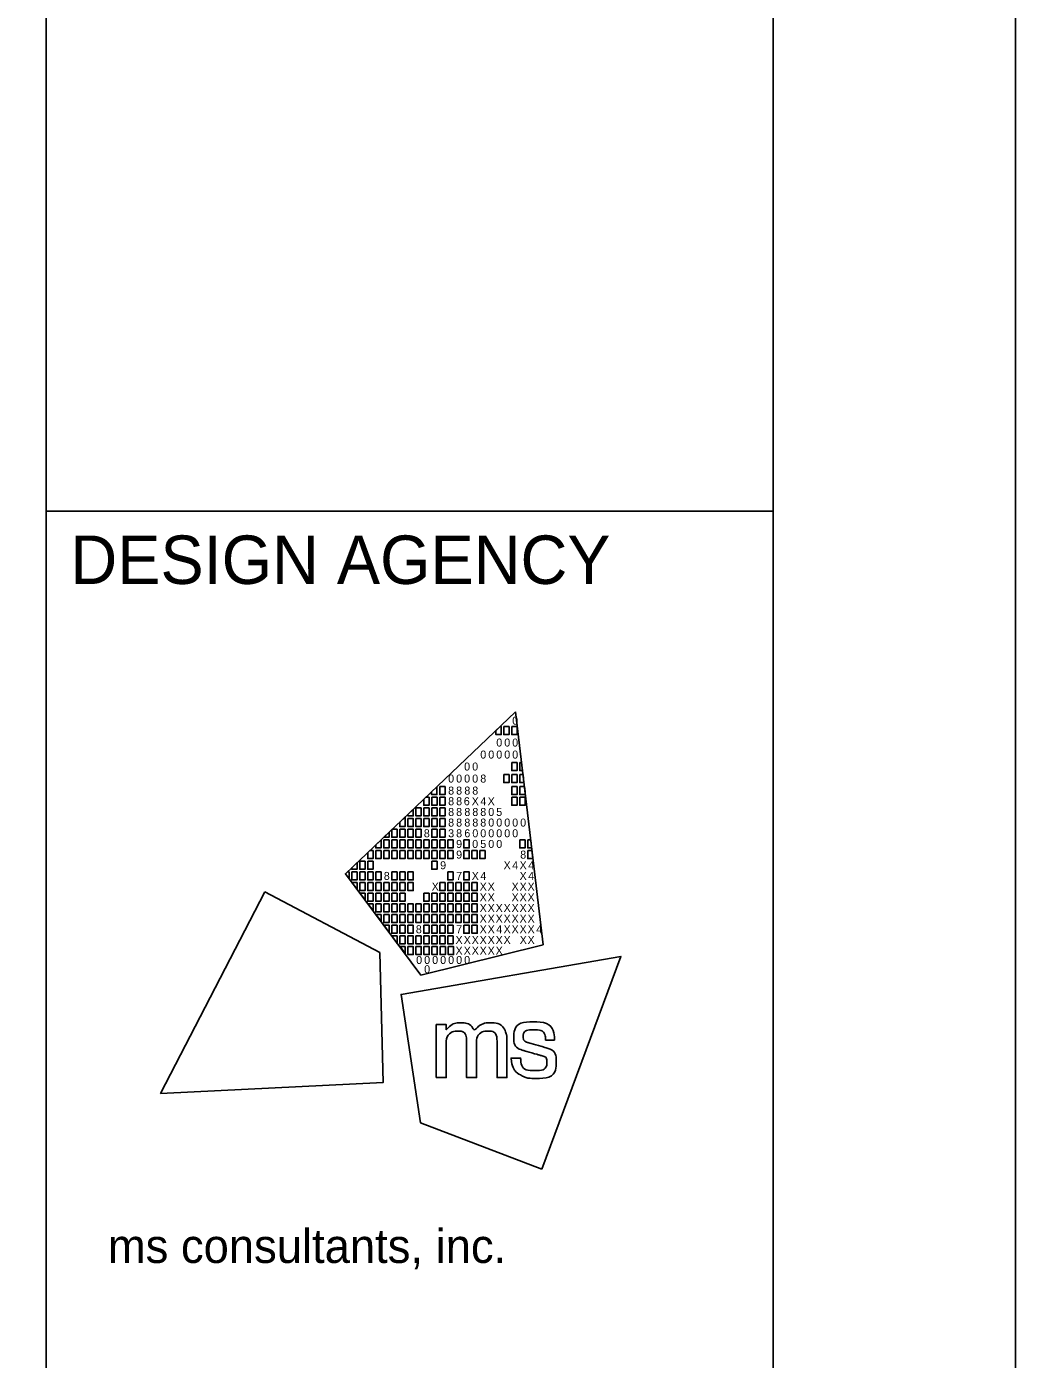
# Model space of a CAD drawing. Extents: x -10 to 89.7, y -4.8 to 22.
# Drawn here: x 31.96 to 34, y 2.75 to 5.5 of the extents above; entities that cross this region are included whole.
import ezdxf

# ---------------------------------------------------------------- set-up
doc = ezdxf.new("R2010")
doc.units = 0
for name, color, linetype in [('Default', 7, 'Continuous'), ('GM_X_Minor_Lake', 7, 'Continuous'), ('GM_X_Minor_River', 7, 'Continuous'), ('SH_Text', 7, 'Continuous')]:
    doc.layers.add(name, color=color, linetype=linetype)

msp = doc.modelspace()

# ---------------------------------------------------------------- linework, layer by layer
at = {"layer": 'Default'}
for p, q in [((32.6176, 3.7519), (32.9688, 4.0861)), ((32.9688, 4.0861), (32.9688, 4.0861)), ((32.9688, 4.0861), (33.0253, 3.6052)), ((32.773, 3.543), (32.6176, 3.7519)), ((33.0253, 3.6052), (32.773, 3.543))]:
    msp.add_line(p, q, dxfattribs=at)
for points in [[(32.9279, 4.0472), (32.9369, 4.0558), (32.939, 4.0558), (32.939, 4.0393), (32.9279, 4.0393)], [(32.9444, 4.0558), (32.9554, 4.0558), (32.9554, 4.0393), (32.9444, 4.0393)], [(32.9609, 4.0558), (32.9719, 4.0558), (32.9719, 4.0393), (32.9609, 4.0393)], [(32.9606, 3.9815), (32.9716, 3.9815), (32.9716, 3.965), (32.9606, 3.965)], [(32.9771, 3.9815), (32.9811, 3.9815), (32.983, 3.965), (32.9771, 3.965)], [(32.9442, 3.9567), (32.9552, 3.9567), (32.9552, 3.9402), (32.9442, 3.9402)], [(32.9606, 3.9567), (32.9716, 3.9567), (32.9716, 3.9402), (32.9606, 3.9402)], [(32.9771, 3.9567), (32.984, 3.9567), (32.9859, 3.9402), (32.9771, 3.9402)], [(32.7954, 3.9211), (32.8064, 3.9316), (32.8064, 3.9154), (32.7954, 3.9154)], [(32.7958, 3.9099), (32.8068, 3.9099), (32.8068, 3.8934), (32.7958, 3.8934)], [(32.8123, 3.9319), (32.8233, 3.9319), (32.8233, 3.9154), (32.8123, 3.9154)], [(32.8123, 3.9099), (32.8233, 3.9099), (32.8233, 3.8934), (32.8123, 3.8934)], [(32.9606, 3.9319), (32.9716, 3.9319), (32.9716, 3.9154), (32.9606, 3.9154)], [(32.9606, 3.9099), (32.9716, 3.9099), (32.9716, 3.8934), (32.9606, 3.8934)], [(32.9771, 3.9319), (32.9869, 3.9319), (32.9881, 3.9218), (32.9881, 3.9154), (32.9771, 3.9154)], [(32.9771, 3.9099), (32.9881, 3.9099), (32.9881, 3.8934), (32.9771, 3.8934)], [(32.7628, 3.8879), (32.7738, 3.8879), (32.7738, 3.8714), (32.7628, 3.8714)], [(32.7793, 3.8879), (32.7903, 3.8879), (32.7903, 3.8714), (32.7793, 3.8714)], [(32.7958, 3.8879), (32.8068, 3.8879), (32.8068, 3.8714), (32.7958, 3.8714)], [(32.8123, 3.8879), (32.8233, 3.8879), (32.8233, 3.8714), (32.8123, 3.8714)], [(32.7463, 3.8659), (32.7573, 3.8659), (32.7573, 3.8494), (32.7463, 3.8494)], [(32.7628, 3.8659), (32.7738, 3.8659), (32.7738, 3.8494), (32.7628, 3.8494)], [(32.7793, 3.8659), (32.7903, 3.8659), (32.7903, 3.8494), (32.7793, 3.8494)], [(32.7958, 3.8659), (32.8068, 3.8659), (32.8068, 3.8494), (32.7958, 3.8494)], [(32.8123, 3.8659), (32.8233, 3.8659), (32.8233, 3.8494), (32.8123, 3.8494)], [(32.7297, 3.8439), (32.7407, 3.8439), (32.7407, 3.8273), (32.7297, 3.8273)], [(32.7463, 3.8439), (32.7573, 3.8439), (32.7573, 3.8273), (32.7463, 3.8273)], [(32.7628, 3.8439), (32.7738, 3.8439), (32.7738, 3.8273), (32.7628, 3.8273)], [(32.7958, 3.8439), (32.8068, 3.8439), (32.8068, 3.8273), (32.7958, 3.8273)], [(32.8123, 3.8439), (32.8233, 3.8439), (32.8233, 3.8273), (32.8123, 3.8273)], [(32.6802, 3.7998), (32.6912, 3.7998), (32.6912, 3.7833), (32.6802, 3.7833)], [(32.6967, 3.8218), (32.7077, 3.8218), (32.7077, 3.8053), (32.6967, 3.8053)], [(32.6967, 3.7998), (32.7077, 3.7998), (32.7077, 3.7833), (32.6967, 3.7833)], [(32.7132, 3.8218), (32.7242, 3.8218), (32.7242, 3.8053), (32.7132, 3.8053)], [(32.7132, 3.7998), (32.7242, 3.7998), (32.7242, 3.7833), (32.7132, 3.7833)], [(32.7297, 3.8218), (32.7407, 3.8218), (32.7407, 3.8053), (32.7297, 3.8053)], [(32.7297, 3.7998), (32.7407, 3.7998), (32.7407, 3.7833), (32.7297, 3.7833)], [(32.7463, 3.8218), (32.7573, 3.8218), (32.7573, 3.8053), (32.7463, 3.8053)], [(32.7463, 3.7998), (32.7573, 3.7998), (32.7573, 3.7833), (32.7463, 3.7833)], [(32.7628, 3.8218), (32.7738, 3.8218), (32.7738, 3.8053), (32.7628, 3.8053)], [(32.7628, 3.7998), (32.7738, 3.7998), (32.7738, 3.7833), (32.7628, 3.7833)], [(32.7793, 3.8218), (32.7903, 3.8218), (32.7903, 3.8053), (32.7793, 3.8053)], [(32.7793, 3.7998), (32.7903, 3.7998), (32.7903, 3.7833), (32.7793, 3.7833)], [(32.7958, 3.8218), (32.8068, 3.8218), (32.8068, 3.8053), (32.7958, 3.8053)], [(32.7958, 3.7998), (32.8068, 3.7998), (32.8068, 3.7833), (32.7958, 3.7833)], [(32.8123, 3.8218), (32.8233, 3.8218), (32.8233, 3.8053), (32.8123, 3.8053)], [(32.8123, 3.7998), (32.8233, 3.7998), (32.8233, 3.7833), (32.8123, 3.7833)], [(32.8288, 3.8218), (32.8398, 3.8218), (32.8398, 3.8053), (32.8288, 3.8053)], [(32.8288, 3.7998), (32.8398, 3.7998), (32.8398, 3.7833), (32.8288, 3.7833)], [(32.8618, 3.8218), (32.8729, 3.8218), (32.8729, 3.8053), (32.8618, 3.8053)], [(32.8618, 3.7998), (32.8729, 3.7998), (32.8729, 3.7833), (32.8618, 3.7833)], [(32.8784, 3.7998), (32.8894, 3.7998), (32.8894, 3.7833), (32.8784, 3.7833)], [(32.8947, 3.7998), (32.9057, 3.7998), (32.9057, 3.7833), (32.8947, 3.7833)], [(32.9771, 3.8218), (32.9881, 3.8218), (32.9881, 3.8053), (32.9771, 3.8053)], [(32.9936, 3.8218), (32.9999, 3.8218), (33.0018, 3.8053), (32.9936, 3.8053)], [(32.9936, 3.7998), (33.0024, 3.7998), (33.0044, 3.7833), (32.9936, 3.7833)], [(32.6472, 3.7778), (32.6582, 3.7778), (32.6582, 3.7613), (32.6472, 3.7613)], [(32.6637, 3.7778), (32.6747, 3.7778), (32.6747, 3.7613), (32.6637, 3.7613)], [(32.7958, 3.7778), (32.8068, 3.7778), (32.8068, 3.7613), (32.7958, 3.7613)], [(32.6307, 3.7558), (32.6417, 3.7558), (32.6417, 3.7393), (32.6307, 3.7393)], [(32.6472, 3.7558), (32.6582, 3.7558), (32.6582, 3.7393), (32.6472, 3.7393)], [(32.6637, 3.7558), (32.6747, 3.7558), (32.6747, 3.7393), (32.6637, 3.7393)], [(32.6802, 3.7558), (32.6912, 3.7558), (32.6912, 3.7393), (32.6802, 3.7393)], [(32.7132, 3.7558), (32.7242, 3.7558), (32.7242, 3.7393), (32.7132, 3.7393)], [(32.7297, 3.7558), (32.7407, 3.7558), (32.7407, 3.7393), (32.7297, 3.7393)], [(32.7463, 3.7558), (32.7573, 3.7558), (32.7573, 3.7393), (32.7463, 3.7393)], [(32.8288, 3.7558), (32.8398, 3.7558), (32.8398, 3.7393), (32.8288, 3.7393)], [(32.8618, 3.7558), (32.8729, 3.7558), (32.8729, 3.7393), (32.8618, 3.7393)], [(32.6307, 3.7338), (32.6417, 3.7338), (32.6417, 3.72)], [(32.6472, 3.7338), (32.6582, 3.7338), (32.6582, 3.7173), (32.6472, 3.7173)], [(32.6637, 3.7338), (32.6747, 3.7338), (32.6747, 3.7173), (32.6637, 3.7173)], [(32.6802, 3.7338), (32.6912, 3.7338), (32.6912, 3.7173), (32.6802, 3.7173)], [(32.6967, 3.7338), (32.7077, 3.7338), (32.7077, 3.7173), (32.6967, 3.7173)], [(32.7132, 3.7338), (32.7242, 3.7338), (32.7242, 3.7173), (32.7132, 3.7173)], [(32.7297, 3.7338), (32.7407, 3.7338), (32.7407, 3.7173), (32.7297, 3.7173)], [(32.7463, 3.7338), (32.7573, 3.7338), (32.7573, 3.7173), (32.7463, 3.7173)], [(32.8123, 3.7338), (32.8233, 3.7338), (32.8233, 3.7173), (32.8123, 3.7173)], [(32.8288, 3.7338), (32.8398, 3.7338), (32.8398, 3.7173), (32.8288, 3.7173)], [(32.8453, 3.7338), (32.8563, 3.7338), (32.8563, 3.7173), (32.8453, 3.7173)], [(32.8618, 3.7338), (32.8729, 3.7338), (32.8729, 3.7173), (32.8618, 3.7173)], [(32.8784, 3.7338), (32.8894, 3.7338), (32.8894, 3.7173), (32.8784, 3.7173)], [(32.6472, 3.7117), (32.6582, 3.7117), (32.6582, 3.698)], [(32.6637, 3.7117), (32.6747, 3.7117), (32.6747, 3.6952), (32.6637, 3.6952)], [(32.6637, 3.6897), (32.6747, 3.6897), (32.6747, 3.676)], [(32.6747, 3.6897), (32.6747, 3.6897), (32.6747, 3.6897)], [(32.6802, 3.7117), (32.6912, 3.7117), (32.6912, 3.6952), (32.6802, 3.6952)], [(32.6802, 3.6897), (32.6912, 3.6897), (32.6912, 3.6732), (32.6802, 3.6732)], [(32.6967, 3.7117), (32.7077, 3.7117), (32.7077, 3.6952), (32.6967, 3.6952)], [(32.6967, 3.6897), (32.7077, 3.6897), (32.7077, 3.6732), (32.6967, 3.6732)], [(32.7132, 3.7117), (32.7242, 3.7117), (32.7242, 3.6952), (32.7132, 3.6952)], [(32.7132, 3.6897), (32.7242, 3.6897), (32.7242, 3.6732), (32.7132, 3.6732)], [(32.7297, 3.7117), (32.7407, 3.7117), (32.7407, 3.6952), (32.7297, 3.6952)], [(32.7297, 3.6897), (32.7407, 3.6897), (32.7407, 3.6732), (32.7297, 3.6732)], [(32.7463, 3.6897), (32.7573, 3.6897), (32.7573, 3.6732), (32.7463, 3.6732)], [(32.7628, 3.6897), (32.7738, 3.6897), (32.7738, 3.6732), (32.7628, 3.6732)], [(32.7793, 3.7117), (32.7903, 3.7117), (32.7903, 3.6952), (32.7793, 3.6952)], [(32.7793, 3.6897), (32.7903, 3.6897), (32.7903, 3.6732), (32.7793, 3.6732)], [(32.7958, 3.7117), (32.8068, 3.7117), (32.8068, 3.6952), (32.7958, 3.6952)], [(32.7958, 3.6897), (32.8068, 3.6897), (32.8068, 3.6732), (32.7958, 3.6732)], [(32.8123, 3.7117), (32.8233, 3.7117), (32.8233, 3.6952), (32.8123, 3.6952)], [(32.8123, 3.6897), (32.8233, 3.6897), (32.8233, 3.6732), (32.8123, 3.6732)], [(32.8288, 3.7117), (32.8398, 3.7117), (32.8398, 3.6952), (32.8288, 3.6952)], [(32.8288, 3.6897), (32.8398, 3.6897), (32.8398, 3.6732), (32.8288, 3.6732)], [(32.8453, 3.7117), (32.8563, 3.7117), (32.8563, 3.6952), (32.8453, 3.6952)], [(32.8453, 3.6897), (32.8563, 3.6897), (32.8563, 3.6732), (32.8453, 3.6732)], [(32.8618, 3.7117), (32.8729, 3.7117), (32.8729, 3.6952), (32.8618, 3.6952)], [(32.8618, 3.6897), (32.8729, 3.6897), (32.8729, 3.6732), (32.8618, 3.6732)], [(32.8784, 3.7117), (32.8894, 3.7117), (32.8894, 3.6952), (32.8784, 3.6952)], [(32.8784, 3.6897), (32.8894, 3.6897), (32.8894, 3.6732), (32.8784, 3.6732)], [(32.6802, 3.6677), (32.6912, 3.6677), (32.6912, 3.654)], [(32.6967, 3.6677), (32.7077, 3.6677), (32.7077, 3.6512), (32.6967, 3.6512)], [(32.7132, 3.6677), (32.7242, 3.6677), (32.7242, 3.6512), (32.7132, 3.6512)], [(32.7297, 3.6677), (32.7407, 3.6677), (32.7407, 3.6512), (32.7297, 3.6512)], [(32.7463, 3.6677), (32.7573, 3.6677), (32.7573, 3.6512), (32.7463, 3.6512)], [(32.7628, 3.6677), (32.7738, 3.6677), (32.7738, 3.6512), (32.7628, 3.6512)], [(32.7793, 3.6677), (32.7903, 3.6677), (32.7903, 3.6512), (32.7793, 3.6512)], [(32.7958, 3.6677), (32.8068, 3.6677), (32.8068, 3.6512), (32.7958, 3.6512)], [(32.8123, 3.6677), (32.8233, 3.6677), (32.8233, 3.6512), (32.8123, 3.6512)], [(32.8288, 3.6677), (32.8398, 3.6677), (32.8398, 3.6512), (32.8288, 3.6512)], [(32.8453, 3.6677), (32.8563, 3.6677), (32.8563, 3.6512), (32.8453, 3.6512)], [(32.8618, 3.6677), (32.8729, 3.6677), (32.8729, 3.6512), (32.8618, 3.6512)], [(32.8784, 3.6677), (32.8894, 3.6677), (32.8894, 3.6512), (32.8784, 3.6512)], [(32.7078, 3.6305), (32.6966, 3.6457), (32.7078, 3.6457)], [(32.7132, 3.6457), (32.7242, 3.6457), (32.7242, 3.6292), (32.7132, 3.6292)], [(32.7297, 3.6457), (32.7407, 3.6457), (32.7407, 3.6292), (32.7297, 3.6292)], [(32.7463, 3.6457), (32.7573, 3.6457), (32.7573, 3.6292), (32.7463, 3.6292)], [(32.7793, 3.6457), (32.7903, 3.6457), (32.7903, 3.6292), (32.7793, 3.6292)], [(32.7958, 3.6457), (32.8068, 3.6457), (32.8068, 3.6292), (32.7958, 3.6292)], [(32.8123, 3.6457), (32.8233, 3.6457), (32.8233, 3.6292), (32.8123, 3.6292)], [(32.8288, 3.6457), (32.8398, 3.6457), (32.8398, 3.6292), (32.8288, 3.6292)], [(32.8618, 3.6457), (32.8729, 3.6457), (32.8729, 3.6292), (32.8618, 3.6292)], [(32.8784, 3.6457), (32.8894, 3.6457), (32.8894, 3.6292), (32.8784, 3.6292)], [(32.724, 3.6082), (32.7132, 3.6237), (32.7242, 3.6237)], [(32.7297, 3.6237), (32.7407, 3.6237), (32.7407, 3.6072), (32.7297, 3.6072)], [(32.7463, 3.6237), (32.7573, 3.6237), (32.7573, 3.6072), (32.7463, 3.6072)], [(32.7628, 3.6237), (32.7738, 3.6237), (32.7738, 3.6072), (32.7628, 3.6072)], [(32.7793, 3.6237), (32.7903, 3.6237), (32.7903, 3.6072), (32.7793, 3.6072)], [(32.7958, 3.6237), (32.8068, 3.6237), (32.8068, 3.6072), (32.7958, 3.6072)], [(32.8123, 3.6237), (32.8233, 3.6237), (32.8233, 3.6072), (32.8123, 3.6072)], [(32.8288, 3.6237), (32.8398, 3.6237), (32.8398, 3.6072), (32.8288, 3.6072)], [(32.7302, 3.6017), (32.7407, 3.6017), (32.7408, 3.5875)], [(32.7463, 3.6017), (32.7573, 3.6017), (32.7573, 3.5852), (32.7463, 3.5852)], [(32.763, 3.6017), (32.774, 3.6017), (32.774, 3.5852), (32.763, 3.5852)], [(32.7794, 3.6017), (32.7904, 3.6017), (32.7904, 3.5852), (32.7794, 3.5852)], [(32.7961, 3.6017), (32.8071, 3.6017), (32.8071, 3.5852), (32.7961, 3.5852)], [(32.813, 3.6017), (32.824, 3.6017), (32.824, 3.5851), (32.813, 3.5851)], [(32.8296, 3.6017), (32.8407, 3.6017), (32.8407, 3.5851), (32.8296, 3.5851)]]:
    msp.add_lwpolyline(points, close=True, dxfattribs=at)
for points in [[(32.7903, 3.9099), (32.7836, 3.9099), (32.7793, 3.9058), (32.7793, 3.8934), (32.7903, 3.8934), (32.7903, 3.9099)], [(32.7573, 3.8849), (32.7463, 3.8744), (32.7463, 3.8714), (32.7573, 3.8714), (32.7573, 3.8849)], [(32.7407, 3.8691), (32.7297, 3.8587), (32.7297, 3.8494), (32.7407, 3.8494), (32.7407, 3.8691)], [(32.7077, 3.8377), (32.6968, 3.8273), (32.7077, 3.8273), (32.7077, 3.8377)], [(32.7242, 3.8439), (32.7142, 3.8439), (32.7132, 3.843), (32.7132, 3.8273), (32.7242, 3.8273), (32.7242, 3.8439)], [(32.6747, 3.7998), (32.6679, 3.7998), (32.6637, 3.7958), (32.6637, 3.7833), (32.6747, 3.7833), (32.6747, 3.7998)], [(32.6912, 3.822), (32.6802, 3.8115), (32.6802, 3.8053), (32.6912, 3.8053), (32.6912, 3.822)], [(32.6417, 3.7749), (32.6307, 3.7644), (32.6307, 3.7613), (32.6417, 3.7613), (32.6417, 3.7749)], [(32.6252, 3.7558), (32.6216, 3.7558), (32.6176, 3.7519), (32.6252, 3.7417), (32.6252, 3.7558)], [(32.4512, 3.7149), (32.2359, 3.2988), (32.6957, 3.3215), (32.6884, 3.5892), (32.4512, 3.7149)], [(33.0229, 3.1422), (33.1859, 3.5814), (32.7324, 3.5029), (32.7722, 3.2381), (33.0229, 3.1422)]]:
    msp.add_lwpolyline(points, dxfattribs=at)
for points in [[(32.8048, 3.3315), (32.8048, 3.3315), (32.8048, 3.4409), (32.8048, 3.4409), (32.8048, 3.4409), (32.8255, 3.4409), (32.8255, 3.4409), (32.8255, 3.4409), (32.8255, 3.4297), (32.8255, 3.4297), (32.8346, 3.4399), (32.8457, 3.4445), (32.8555, 3.4445), (32.8689, 3.4445), (32.8792, 3.4372), (32.8837, 3.4266), (32.8915, 3.4381), (32.905, 3.4446), (32.9166, 3.4446), (32.9325, 3.4446), (32.9451, 3.435), (32.9494, 3.4213), (32.9494, 3.4212), (32.9494, 3.4212), (32.9495, 3.4212), (32.9501, 3.419), (32.9507, 3.4172), (32.9507, 3.4071), (32.9507, 3.4071), (32.9507, 3.3314), (32.9507, 3.3314), (32.9507, 3.3314), (32.9303, 3.3314), (32.9303, 3.3314), (32.9303, 3.3314), (32.9303, 3.4048), (32.9303, 3.4048), (32.9303, 3.4201), (32.9219, 3.4274), (32.9111, 3.4274), (32.8995, 3.4274), (32.888, 3.4171), (32.888, 3.4001), (32.888, 3.4001), (32.888, 3.3315), (32.888, 3.3315), (32.888, 3.3315), (32.8674, 3.3315), (32.8674, 3.3315), (32.8674, 3.3315), (32.8674, 3.4059), (32.8674, 3.4059), (32.8674, 3.4203), (32.8588, 3.4274), (32.8497, 3.4274), (32.8384, 3.4274), (32.8254, 3.417), (32.8254, 3.3962), (32.8254, 3.3962), (32.8254, 3.3315), (32.8254, 3.3315), (32.8254, 3.3315), (32.8048, 3.3315), (32.8048, 3.3315)], [(32.9596, 3.3709), (32.9596, 3.3709), (32.9595, 3.3717), (32.9595, 3.3717), (32.9595, 3.3717), (32.9603, 3.3717), (32.9603, 3.3717), (32.9603, 3.3717), (32.9783, 3.3717), (32.9783, 3.3717), (32.9783, 3.3717), (32.9789, 3.3717), (32.9789, 3.3717), (32.9789, 3.3717), (32.979, 3.371), (32.979, 3.371), (32.9803, 3.3554), (32.9887, 3.346), (33.009, 3.346), (33.0273, 3.346), (33.0333, 3.3554), (33.0333, 3.3631), (33.0333, 3.3732), (33.0256, 3.3758), (33.0175, 3.378), (33.0175, 3.378), (32.987, 3.3867), (32.987, 3.3867), (32.9721, 3.3909), (32.9648, 3.4019), (32.9648, 3.4142), (32.9648, 3.4303), (32.9768, 3.4462), (33.0052, 3.4462), (33.0348, 3.4462), (33.0489, 3.4285), (33.0489, 3.4095), (33.0489, 3.4095), (33.0489, 3.4087), (33.0489, 3.4087), (33.0489, 3.4087), (33.0482, 3.4087), (33.0482, 3.4087), (33.0482, 3.4087), (33.0312, 3.4087), (33.0312, 3.4087), (33.0312, 3.4087), (33.0305, 3.4087), (33.0305, 3.4087), (33.0305, 3.4087), (33.0305, 3.4094), (33.0305, 3.4094), (33.0302, 3.4208), (33.0227, 3.43), (33.0056, 3.43), (32.9891, 3.43), (32.9843, 3.4218), (32.9843, 3.4157), (32.9843, 3.4108), (32.9869, 3.4059), (32.9959, 3.4033), (32.9959, 3.4033), (33.0255, 3.3948), (33.0255, 3.3948), (33.0462, 3.3889), (33.0527, 3.3777), (33.0527, 3.3639), (33.0527, 3.3462), (33.041, 3.3298), (33.0087, 3.3298), (32.9952, 3.3298), (32.9877, 3.3321), (32.9823, 3.3348), (32.9691, 3.3414), (32.961, 3.3536), (32.9596, 3.3709)]]:
    msp.add_open_spline(points, degree=3, dxfattribs=at)
at = {"layer": 'GM_X_Minor_Lake'}
msp.add_line((32.75, 3.5), (32.75, 3.5), dxfattribs=at)
at = {"layer": 'GM_X_Minor_River'}
for p, q in [((32, 0.5), (32, 21.5)), ((32, 4.5), (33.5, 4.5))]:
    msp.add_line(p, q, dxfattribs=at)
msp.add_lwpolyline([(1.5, 21.5), (33.5, 21.5), (33.5, 0.5), (1.5, 0.5)], close=True, dxfattribs=at)
at = {"layer": 'SH_Text'}
msp.add_lwpolyline([(0, 0), (34, 0), (34, 22), (0, 22)], close=True, dxfattribs=at)

# ---------------------------------------------------------------- texts
at = {"layer": 'Default'}
for s, p in [('0', (32.9617, 4.0597)), ('0', (32.9288, 4.0145)), ('0', (32.9453, 4.0145)), ('0', (32.9617, 4.0145)), ('0', (32.8958, 3.9897)), ('0', (32.9123, 3.9897)), ('0', (32.9288, 3.9897)), ('0', (32.9453, 3.9897)), ('0', (32.9617, 3.9897)), ('0', (32.8625, 3.965)), ('0', (32.8791, 3.965)), ('0', (32.8295, 3.9402)), ('0', (32.846, 3.9402)), ('0', (32.8625, 3.9402)), ('0', (32.8791, 3.9402)), ('8', (32.8958, 3.9402)), ('8', (32.8295, 3.9154)), ('8', (32.8295, 3.8934)), ('8', (32.846, 3.9154)), ('8', (32.846, 3.8934)), ('6', (32.8618, 3.8934)), ('8', (32.8629, 3.9154)), ('X', (32.8781, 3.8934)), ('8', (32.8793, 3.9154)), ('4', (32.8959, 3.8934)), ('X', (32.911, 3.8934)), ('8', (32.8295, 3.8713)), ('8', (32.846, 3.8713)), ('8', (32.8629, 3.8713)), ('8', (32.8794, 3.8713)), ('8', (32.8958, 3.8713)), ('0', (32.9123, 3.8713)), ('5', (32.9287, 3.8713)), ('8', (32.8295, 3.8494)), ('8', (32.846, 3.8494)), ('8', (32.8629, 3.8494)), ('8', (32.8794, 3.8494)), ('8', (32.8958, 3.8494)), ('0', (32.9123, 3.8494)), ('0', (32.9288, 3.8494)), ('0', (32.9453, 3.8494)), ('0', (32.9617, 3.8494)), ('0', (32.9782, 3.8494)), ('8', (32.7793, 3.8273)), ('3', (32.8295, 3.8273)), ('8', (32.846, 3.8273)), ('6', (32.8629, 3.8273)), ('0', (32.8794, 3.8273)), ('0', (32.8958, 3.8273)), ('0', (32.9123, 3.8273)), ('0', (32.9288, 3.8273)), ('0', (32.9453, 3.8273)), ('0', (32.9617, 3.8273)), ('9', (32.846, 3.8053)), ('9', (32.846, 3.7833)), ('0', (32.8791, 3.8053)), ('5', (32.8958, 3.8053)), ('0', (32.9123, 3.8053)), ('0', (32.9288, 3.8053)), ('8', (32.9782, 3.7833)), ('9', (32.813, 3.7613)), ('X', (32.9439, 3.7613)), ('4', (32.9617, 3.7613)), ('X', (32.9769, 3.7613)), ('4', (32.9947, 3.7613)), ('8', (32.6967, 3.7393)), ('7', (32.846, 3.7393)), ('X', (32.8781, 3.7393)), ('4', (32.8959, 3.7393)), ('X', (32.9769, 3.7393)), ('4', (32.9947, 3.7393)), ('X', (32.7955, 3.7173)), ('X', (32.8945, 3.7173)), ('X', (32.911, 3.7173)), ('X', (32.9604, 3.7173)), ('X', (32.9769, 3.7173)), ('X', (32.9934, 3.7173)), ('X', (32.8945, 3.6952)), ('X', (32.8945, 3.6732)), ('X', (32.911, 3.6952)), ('X', (32.911, 3.6732)), ('X', (32.9275, 3.6732)), ('X', (32.9439, 3.6732)), ('X', (32.9604, 3.6952)), ('X', (32.9604, 3.6732)), ('X', (32.9769, 3.6952)), ('X', (32.9769, 3.6732)), ('X', (32.9934, 3.6952)), ('X', (32.9934, 3.6732)), ('X', (32.8945, 3.6512)), ('X', (32.911, 3.6512)), ('X', (32.9275, 3.6512)), ('X', (32.9439, 3.6512)), ('X', (32.9604, 3.6512)), ('X', (32.9769, 3.6512)), ('X', (32.9934, 3.6512)), ('8', (32.7628, 3.6292)), ('7', (32.846, 3.6292)), ('X', (32.8945, 3.6292)), ('X', (32.911, 3.6292)), ('4', (32.9288, 3.6292)), ('X', (32.9439, 3.6292)), ('X', (32.9604, 3.6292)), ('X', (32.9769, 3.6292)), ('X', (32.9934, 3.6292)), ('4', (33.0112, 3.6292)), ('X', (32.8447, 3.6072)), ('X', (32.8616, 3.6072)), ('X', (32.8781, 3.6072)), ('X', (32.8945, 3.6072)), ('X', (32.911, 3.6072)), ('X', (32.9275, 3.6072)), ('X', (32.9439, 3.6072)), ('X', (32.9772, 3.6072)), ('X', (32.9934, 3.6072)), ('0', (32.7635, 3.5659)), ('0', (32.78, 3.5659)), ('0', (32.7965, 3.5659)), ('0', (32.813, 3.5659)), ('0', (32.8295, 3.5659)), ('X', (32.8447, 3.5851)), ('0', (32.846, 3.5659)), ('X', (32.8616, 3.5851)), ('0', (32.8625, 3.5659)), ('X', (32.8781, 3.5851)), ('X', (32.8945, 3.5851)), ('X', (32.911, 3.5851)), ('X', (32.9275, 3.5851)), ('0', (32.78, 3.5467))]:
    msp.add_text(s, height=0.0165, rotation=360, dxfattribs=at).set_placement(p)
at = {"layer": 'GM_X_Minor_Lake'}
msp.add_text('DESIGN AGENCY', height=0.1, dxfattribs=at).set_placement((32.05, 4.35))
at = {"layer": 'GM_X_Minor_River'}
msp.add_text('ms consultants, inc.', height=0.07, rotation=360, dxfattribs=at).set_placement((32.1273, 2.9489))

doc.saveas('drawing.dxf')
